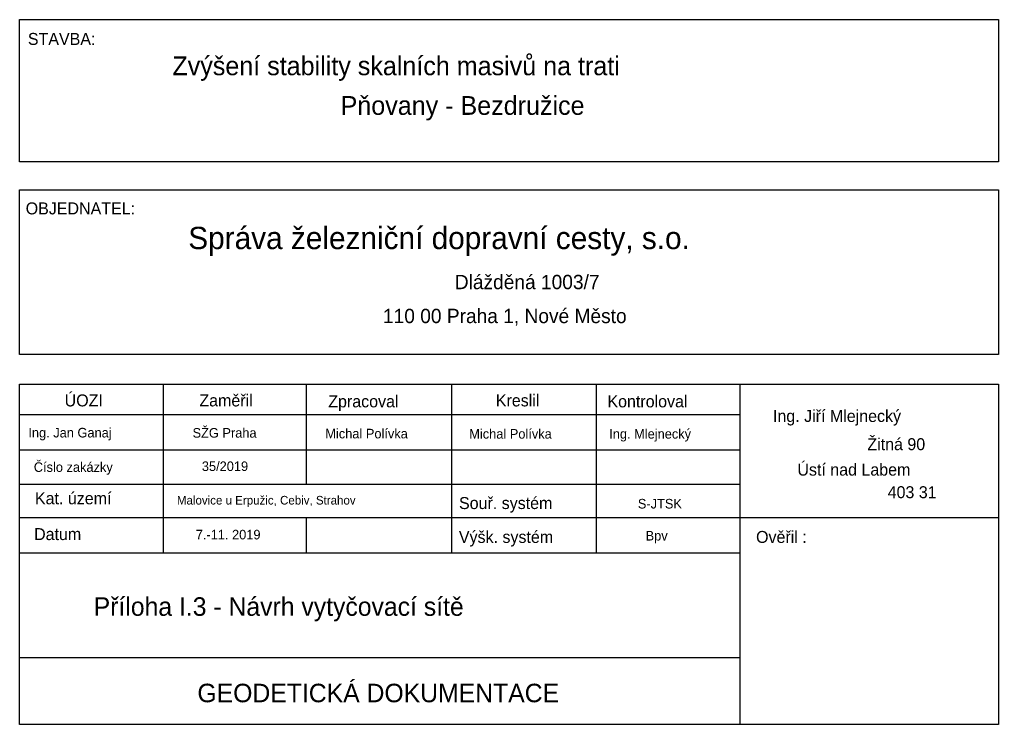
# Model space of a CAD drawing. Extents: x -879530 to -879371, y -1019242 to -1019127.
import ezdxf

# ---------------------------------------------------------------- set-up
doc = ezdxf.new("R2010")
doc.units = 0
doc.layers.add('LEGENDA', color=7, linetype='Continuous')
doc.layers.add('tabulka', color=7, linetype='Continuous')

msp = doc.modelspace()

# ---------------------------------------------------------------- linework, layer by layer
at = {"layer": 'tabulka'}
for p, q in [((-879530.09, -1019186.45), (-879371.44, -1019186.45)), ((-879506.8, -1019186.45), (-879506.8, -1019213.77)), ((-879483.66, -1019186.45), (-879483.66, -1019202.65)), ((-879460.06, -1019186.45), (-879460.06, -1019213.77)), ((-879436.61, -1019186.45), (-879436.61, -1019213.77)), ((-879413.31, -1019241.58), (-879413.31, -1019186.45)), ((-879530.09, -1019191.36), (-879413.31, -1019191.36)), ((-879530.09, -1019197.07), (-879413.31, -1019197.07)), ((-879530.09, -1019202.65), (-879413.31, -1019202.65)), ((-879530.09, -1019208.07), (-879371.44, -1019208.07)), ((-879483.66, -1019208.07), (-879483.66, -1019213.77)), ((-879530.09, -1019213.77), (-879413.31, -1019213.77)), ((-879530.09, -1019230.76), (-879413.31, -1019230.76))]:
    msp.add_line(p, q, dxfattribs=at)
for points in [[(-879530.09, -1019127.36), (-879371.44, -1019127.36), (-879371.44, -1019150.43), (-879530.09, -1019150.43)], [(-879530.09, -1019154.95), (-879371.44, -1019154.95), (-879371.44, -1019181.64), (-879530.09, -1019181.64)]]:
    msp.add_lwpolyline(points, close=True, dxfattribs=at)
msp.add_lwpolyline([(-879371.44, -1019186.45), (-879371.44, -1019241.58), (-879530.09, -1019241.58), (-879530.09, -1019186.45)], dxfattribs=at)

# ---------------------------------------------------------------- texts
at = {"layer": 'LEGENDA'}
for s, p in [('Zvýšení stability skalních masivů na trati', (-879505.32, -1019136.38)), ('Pňovany - Bezdružice', (-879478.06, -1019142.8))]:
    msp.add_text(s, height=3.04, dxfattribs=at).set_placement(p)
at = {"layer": 'tabulka'}
for s, height, p in [('STAVBA:', 1.94, (-879528.75, -1019131.47)), ('OBJEDNATEL:', 1.94, (-879529.1, -1019158.93)), ('Správa železniční dopravní cesty, s.o.', 3.61, (-879502.75, -1019164.56)), ('Dlážděná 1003/7', 2.32, (-879459.55, -1019171.05)), ('110 00 Praha 1, Nové Město', 2.32, (-879471.19, -1019176.55)), ('ÚOZI', 1.94, (-879522.79, -1019190.05)), ('Zaměřil', 1.94, (-879500.95, -1019190.05)), ('Zpracoval', 1.94, (-879480.06, -1019190.2)), ('Kreslil', 1.94, (-879452.9, -1019190.05)), ('Kontroloval', 1.94, (-879434.81, -1019190.2)), ('Ing. Jiří Mlejnecký', 1.94, (-879407.98, -1019192.57)), ('Ing. Jan Ganaj', 1.552, (-879528.67, -1019195.08)), ('SŽG Praha', 1.552, (-879502.06, -1019195.11)), ('Michal Polívka', 1.552, (-879480.54, -1019195.23)), ('Michal Polívka', 1.552, (-879457.21, -1019195.27)), ('Ing. Mlejnecký', 1.552, (-879434.52, -1019195.27)), ('Žitná 90', 1.94, (-879392.68, -1019197.14)), ('Číslo zakázky', 1.552, (-879527.79, -1019200.66)), ('35/2019', 1.552, (-879500.55, -1019200.52)), ('Ústí nad Labem', 1.94, (-879404.02, -1019201.26)), ('403 31', 1.94, (-879389.39, -1019204.92)), ('Kat. území', 1.94, (-879527.6, -1019205.91)), ('Malovice u Erpužic, Cebiv, Strahov', 1.3968, (-879504.59, -1019205.95)), ('Souř. systém', 1.94, (-879458.87, -1019206.68)), ('S-JTSK', 1.552, (-879429.88, -1019206.59)), ('Datum', 1.94, (-879527.74, -1019211.71)), ('7.-11. 2019', 1.552, (-879501.54, -1019211.6)), ('Výšk. systém', 1.94, (-879458.89, -1019212.17)), ('Bpv', 1.552, (-879428.62, -1019211.78)), ('Ověřil :', 1.94, (-879410.72, -1019212.17)), ('Příloha I.3 - Návrh vytyčovací sítě', 3, (-879518.08, -1019223.98)), ('GEODETICKÁ DOKUMENTACE ', 3, (-879501.27, -1019237.99))]:
    msp.add_text(s, height=height, dxfattribs=at).set_placement(p)

doc.saveas('drawing.dxf')
